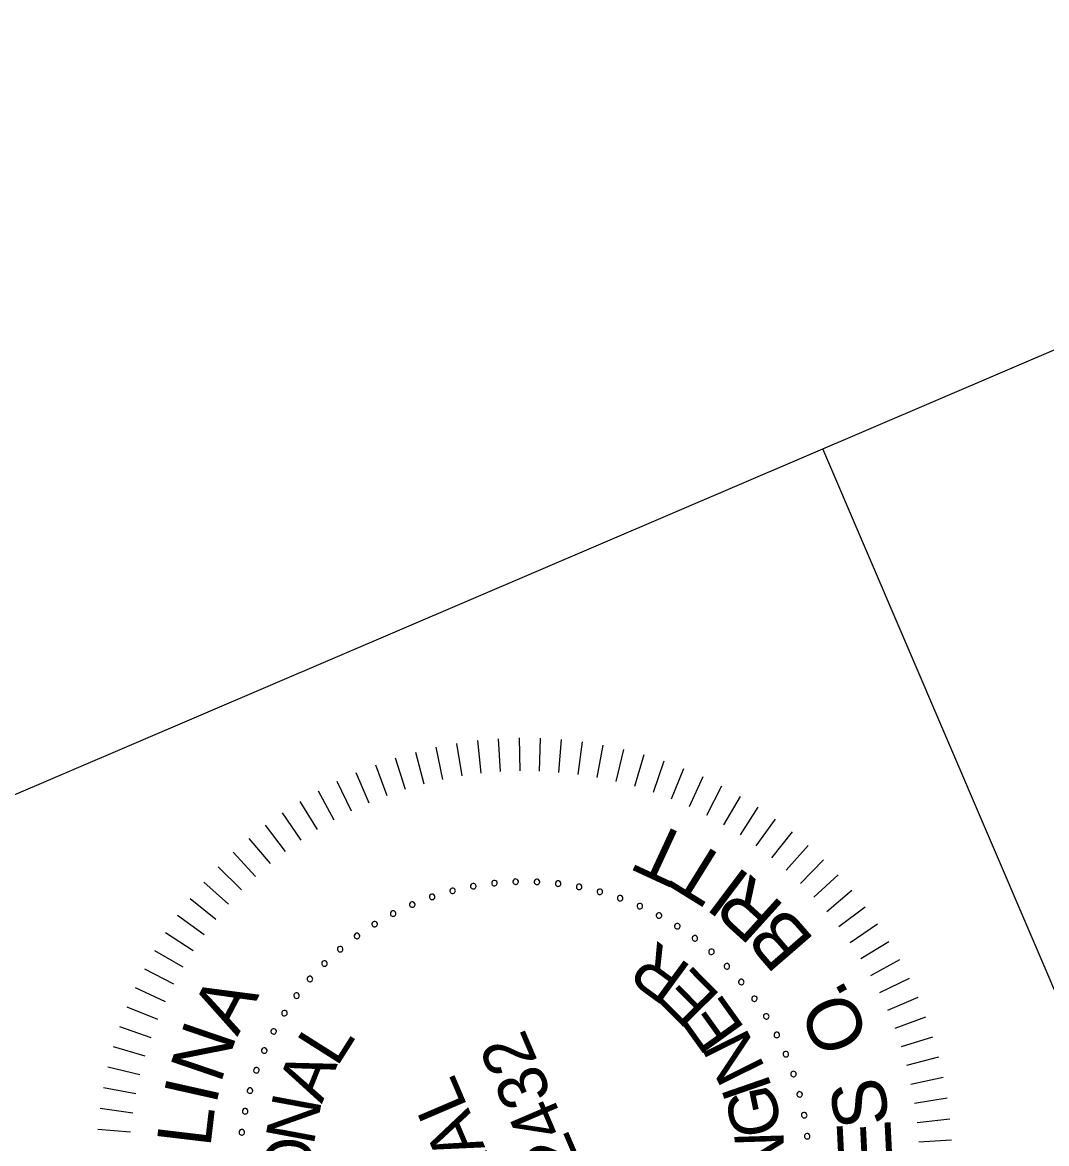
# Model space of a CAD drawing. Extents: x 1550250 to 1553210, y 808906 to 812497.
# Drawn here: x 1551944.7 to 1552075.2, y 811622.3 to 811765.1 of the extents above; entities that cross this region are included whole.
import ezdxf

# ---------------------------------------------------------------- set-up
doc = ezdxf.new("R2010")
doc.units = 0
doc.layers.add('Old_Level_50', color=7, linetype='Continuous')
doc.layers.add('Sheet_Title_CELL', color=7, linetype='Continuous')

msp = doc.modelspace()

# ---------------------------------------------------------------- linework, layer by layer
at = {"layer": 'Old_Level_50'}
for p, q in [((1552002.67, 811673.62), (1552003.13, 811669.45)), ((1552005.34, 811673.85), (1552005.59, 811669.67)), ((1552008.01, 811673.95), (1552008.06, 811669.76)), ((1552010.69, 811673.91), (1552010.53, 811669.72)), ((1552013.36, 811673.75), (1552012.99, 811669.57)), ((1552016.02, 811673.45), (1552015.45, 811669.3)), ((1551994.78, 811672.16), (1551995.85, 811668.1)), ((1551997.39, 811672.78), (1551998.25, 811668.67)), ((1552000.02, 811673.26), (1552000.68, 811669.12)), ((1552018.66, 811673.03), (1552017.89, 811668.9)), ((1552021.27, 811672.47), (1552020.3, 811668.39)), ((1551992.21, 811671.42), (1551993.48, 811667.42)), ((1552023.86, 811671.79), (1552022.69, 811667.76)), ((1552026.41, 811670.98), (1552025.05, 811667.01)), ((1551987.2, 811669.55), (1551988.85, 811665.7)), ((1551989.68, 811670.55), (1551991.14, 811666.61)), ((1552028.92, 811670.04), (1552027.36, 811666.15)), ((1551984.76, 811668.44), (1551986.6, 811664.67)), ((1552031.38, 811668.99), (1552029.63, 811665.18)), ((1552033.78, 811667.81), (1552031.85, 811664.09)), ((1551982.39, 811667.21), (1551984.41, 811663.53)), ((1552036.13, 811666.52), (1552034.01, 811662.9)), ((1551980.07, 811665.86), (1551982.27, 811662.29)), ((1552038.4, 811665.12), (1552036.12, 811661.6)), ((1551977.83, 811664.41), (1551980.2, 811660.95)), ((1552040.61, 811663.6), (1552038.15, 811660.2)), ((1551975.66, 811662.84), (1551978.2, 811659.5)), ((1551973.57, 811661.17), (1551976.27, 811657.96)), ((1552042.74, 811661.98), (1552040.12, 811658.71)), ((1551971.57, 811659.4), (1551974.42, 811656.32)), ((1552044.79, 811660.26), (1552042.01, 811657.12)), ((1552046.74, 811658.43), (1552043.81, 811655.43)), ((1551969.65, 811657.53), (1551972.65, 811654.6)), ((1552048.61, 811656.52), (1552045.54, 811653.67)), ((1551967.83, 811655.57), (1551970.97, 811652.79)), ((1551966.1, 811653.52), (1551969.38, 811650.9)), ((1552050.38, 811654.51), (1552047.17, 811651.81)), ((1552052.06, 811652.42), (1552048.72, 811649.89)), ((1551964.48, 811651.39), (1551967.88, 811648.94)), ((1551962.97, 811649.19), (1551966.48, 811646.9)), ((1552053.62, 811650.25), (1552050.16, 811647.88)), ((1552055.08, 811648.01), (1552051.51, 811645.81)), ((1551961.56, 811646.91), (1551965.18, 811644.8)), ((1552056.43, 811645.7), (1552052.75, 811643.68)), ((1551960.27, 811644.57), (1551963.99, 811642.63)), ((1551959.1, 811642.16), (1551962.91, 811640.41)), ((1552057.66, 811643.32), (1552053.89, 811641.48)), ((1552058.77, 811640.89), (1552054.91, 811639.24)), ((1551958.04, 811639.7), (1551961.93, 811638.14)), ((1552059.76, 811638.4), (1552055.83, 811636.94)), ((1551957.11, 811637.2), (1551961.07, 811635.83)), ((1552060.63, 811635.87), (1552056.63, 811634.61)), ((1551956.3, 811634.65), (1551960.32, 811633.48)), ((1551955.61, 811632.06), (1551959.69, 811631.09)), ((1552061.38, 811633.3), (1552057.32, 811632.23)), ((1552061.99, 811630.7), (1552057.89, 811629.83)), ((1551955.06, 811629.44), (1551959.18, 811628.67)), ((1552062.48, 811628.07), (1552058.34, 811627.4)), ((1551954.63, 811626.8), (1551958.79, 811626.23)), ((1552062.84, 811625.42), (1552058.67, 811624.95)), ((1551954.34, 811624.14), (1551958.51, 811623.78)), ((1552063.07, 811622.75), (1552058.88, 811622.49))]:
    msp.add_line(p, q, dxfattribs=at)
for centre, start, end in [((1552002.16, 811655.08), 10.3165, 190.3165), ((1552002.16, 811655.08), 190.3165, 10.3165), ((1552004.84, 811655.47), 10.3165, 190.3165), ((1552004.84, 811655.47), 190.3165, 10.3165), ((1552007.55, 811655.65), 10.3165, 190.3165), ((1552007.55, 811655.65), 190.3165, 10.3165), ((1552010.26, 811655.63), 10.3165, 190.3165), ((1552010.26, 811655.63), 190.3165, 10.3165), ((1552012.96, 811655.41), 10.3165, 190.3165), ((1552012.96, 811655.41), 190.3165, 10.3165), ((1552015.63, 811654.99), 10.3165, 190.3165), ((1552015.63, 811654.99), 190.3165, 10.3165), ((1551996.92, 811653.72), 10.3165, 190.3165), ((1551996.92, 811653.72), 190.3165, 10.3165), ((1551999.52, 811654.5), 10.3165, 190.3165), ((1551999.52, 811654.5), 190.3165, 10.3165), ((1552018.27, 811654.37), 10.3165, 190.3165), ((1552018.27, 811654.37), 190.3165, 10.3165), ((1552020.85, 811653.55), 10.3165, 190.3165), ((1552020.85, 811653.55), 190.3165, 10.3165), ((1551994.39, 811652.74), 10.3165, 190.3165), ((1551994.39, 811652.74), 190.3165, 10.3165), ((1552023.37, 811652.54), 10.3165, 190.3165), ((1552023.37, 811652.54), 190.3165, 10.3165), ((1551989.59, 811650.25), 10.3165, 190.3165), ((1551991.94, 811651.59), 10.3165, 190.3165), ((1551991.94, 811651.59), 190.3165, 10.3165), ((1552025.8, 811651.35), 10.3165, 190.3165), ((1552025.8, 811651.35), 190.3165, 10.3165), ((1551989.59, 811650.25), 190.3165, 10.3165), ((1552028.14, 811649.98), 10.3165, 190.3165), ((1552028.14, 811649.98), 190.3165, 10.3165), ((1551987.34, 811648.74), 10.3165, 190.3165), ((1551987.34, 811648.74), 190.3165, 10.3165), ((1552030.37, 811648.44), 10.3165, 190.3165), ((1552030.37, 811648.44), 190.3165, 10.3165), ((1551985.21, 811647.06), 10.3165, 190.3165), ((1551985.21, 811647.06), 190.3165, 10.3165), ((1552032.48, 811646.73), 10.3165, 190.3165), ((1552032.48, 811646.73), 190.3165, 10.3165), ((1551983.21, 811645.23), 10.3165, 190.3165), ((1551983.21, 811645.23), 190.3165, 10.3165), ((1552034.45, 811644.88), 10.3165, 190.3165), ((1552034.45, 811644.88), 190.3165, 10.3165), ((1551981.35, 811643.26), 10.3165, 190.3165), ((1551981.35, 811643.26), 190.3165, 10.3165), ((1552036.28, 811642.88), 10.3165, 190.3165), ((1552036.28, 811642.88), 190.3165, 10.3165), ((1551979.65, 811641.15), 10.3165, 190.3165), ((1551979.65, 811641.15), 190.3165, 10.3165), ((1552037.95, 811640.75), 10.3165, 190.3165), ((1552037.95, 811640.75), 190.3165, 10.3165), ((1551978.1, 811638.92), 10.3165, 190.3165), ((1551978.1, 811638.92), 190.3165, 10.3165), ((1552039.46, 811638.5), 10.3165, 190.3165), ((1552039.46, 811638.5), 190.3165, 10.3165), ((1551976.73, 811636.59), 10.3165, 190.3165), ((1551976.73, 811636.59), 190.3165, 10.3165), ((1552040.8, 811636.14), 10.3165, 190.3165), ((1552040.8, 811636.14), 190.3165, 10.3165), ((1551975.54, 811634.15), 10.3165, 190.3165), ((1551975.54, 811634.15), 190.3165, 10.3165), ((1552041.96, 811633.69), 10.3165, 190.3165), ((1552041.96, 811633.69), 190.3165, 10.3165), ((1551974.53, 811631.64), 10.3165, 190.3165), ((1551974.53, 811631.64), 190.3165, 10.3165), ((1552042.93, 811631.16), 10.3165, 190.3165), ((1552042.93, 811631.16), 190.3165, 10.3165), ((1551973.72, 811629.05), 10.3165, 190.3165), ((1551973.72, 811629.05), 190.3165, 10.3165), ((1552043.71, 811628.57), 10.3165, 190.3165), ((1552043.71, 811628.57), 190.3165, 10.3165), ((1551973.1, 811626.42), 10.3165, 190.3165), ((1551973.1, 811626.42), 190.3165, 10.3165), ((1552044.3, 811625.92), 10.3165, 190.3165), ((1552044.3, 811625.92), 190.3165, 10.3165), ((1551972.67, 811623.74), 10.3165, 190.3165), ((1551972.67, 811623.74), 190.3165, 10.3165), ((1552044.68, 811623.24), 10.3165, 190.3165), ((1552044.68, 811623.24), 190.3165, 10.3165)]:
    msp.add_arc(centre, 0.352, start, end, dxfattribs=at)
at = {"layer": 'Sheet_Title_CELL'}
for p, q in [((1552173.52, 811765.06), (1551919.79, 811656.45)), ((1552195.84, 811362.24), (1552046.65, 811710.76))]:
    msp.add_line(p, q, dxfattribs=at)

# ---------------------------------------------------------------- texts
at = {"layer": 'Old_Level_50'}
for s, height, rotation, p in [('T', 6.87, 155.1501, (1552030.24, 811661.08)), ('T', 6.87, 148.1926, (1552035.12, 811658.16)), ('I', 6.87, 143.0357, (1552037.71, 811656.21)), ('R', 6.87, 137.8788, (1552041.99, 811652.46)), ('B', 6.87, 130.9213, (1552045.75, 811648.18)), ('R', 6.25, 143.7493, (1552030.12, 811644.75)), ('E', 6.25, 134.5994, (1552033.79, 811641.09)), ('A', 6.87, 62.2934, (1551972.11, 811635.85)), ('.', 6.87, 119.352, (1552050.16, 811641.23)), ('E', 6.25, 125.6424, (1552036.86, 811636.91)), ('O', 6.87, 113.4452, (1552052.72, 811635.6)), ('N', 6.87, 71.1486, (1551969.94, 811629.8)), ('L', 6.25, 57.6532, (1551984.76, 811631.92)), ('052432', 6.291, 113.1736, (1552019.61, 811611.28)), ('N', 6.25, 116.2998, (1552039.42, 811631.9)), ('A', 6.25, 68.3097, (1551982.87, 811627.29)), ('SEAL', 6.291, 113.1736, (1552008.11, 811611.5)), ('I', 6.25, 109.0805, (1552040.27, 811629.31)), ('I', 6.87, 77.3672, (1551969.39, 811627.1)), ('G', 6.25, 101.6685, (1552041.55, 811623.83)), ('S', 6.87, 99.7759, (1552055.25, 811624.97)), ('N', 6.25, 79.4409, (1551981.8, 811621.94)), ('L', 6.87, 83.2344, (1551968.66, 811621.71)), ('E', 6.87, 92.8185, (1552055.57, 811619.29)), ('O', 6.25, 90.5721, (1551981.82, 811616.71)), ('N', 6.25, 91.7477, (1552041.82, 811617.99))]:
    msp.add_text(s, height=height, rotation=rotation, dxfattribs=at).set_placement(p)

doc.saveas('drawing.dxf')
